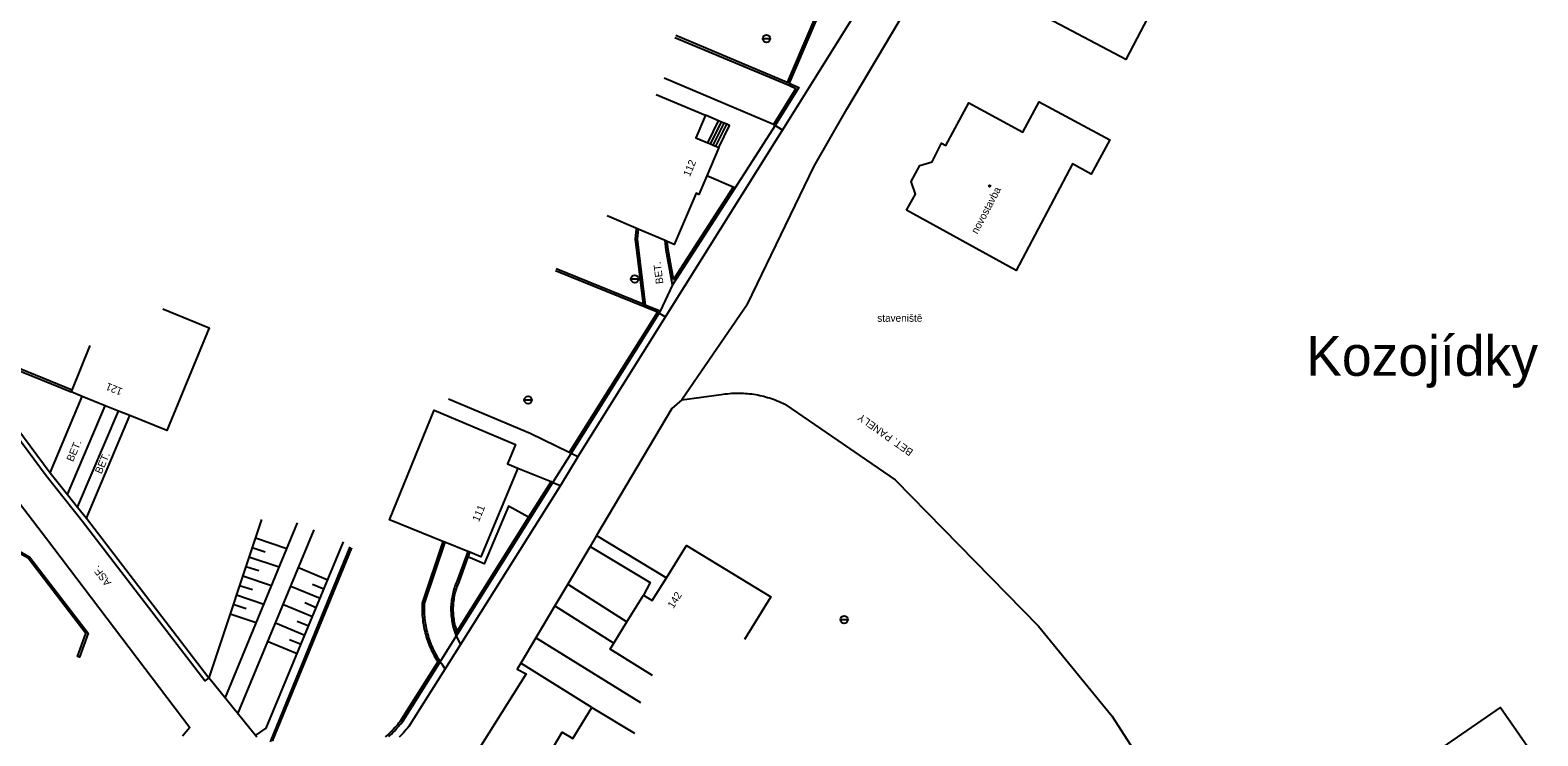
# Model space of a CAD drawing. Extents: x -544674 to -541478, y -1199076 to -1195527.
# Drawn here: x -543774 to -543623.1, y -1197058.3 to -1196987.7 of the extents above; entities that cross this region are included whole.
import ezdxf

# ---------------------------------------------------------------- set-up
doc = ezdxf.new("R2010")
doc.units = 0
for name, color, linetype in [('BUDOVY_MĚŘ', 7, 'Continuous'), ('BUDOVY_NEMĚŘ', 7, 'Continuous'), ('NÁZVY_SÍDEL_JEDNOTKY', 7, 'Continuous'), ('POMOC_POPIS', 7, 'Continuous'), ('ROZHRANÍ_PLOCH', 7, 'Continuous'), ('VÝŠKOPIS', 7, 'Continuous'), ('ZN_BUDOV', 7, 'Continuous'), ('ZN_DOPLŇKOVÉ', 7, 'Continuous'), ('Č_POPIS_ORIENT', 7, 'Continuous')]:
    doc.layers.add(name, color=color, linetype=linetype)

msp = doc.modelspace()

# ---------------------------------------------------------------- linework, layer by layer
at = {"layer": 'BUDOVY_MĚŘ'}
for points in [[(-543675.17, -1196984.9), (-543673.76, -1196981.94), (-543671.67, -1196978.25), (-543667.07, -1196980.67), (-543665.24, -1196977.07), (-543658.12, -1196980.83), (-543660.21, -1196984.79), (-543661.09, -1196984.33), (-543664.37, -1196990.58), (-543675.17, -1196984.9)], [(-543711.37, -1196994.08), (-543706.44, -1196996.17)], [(-543686.31, -1197005.69), (-543685.4, -1197004.07), (-543685.83, -1197002.8), (-543684.98, -1197001.22), (-543683.73, -1197000.85), (-543682.79, -1196998.98), (-543682.36, -1196999.2), (-543680.07, -1196994.92), (-543674.66, -1196997.85), (-543673.02, -1196994.82), (-543665.97, -1196998.64), (-543667.82, -1197002.06), (-543669.69, -1197001.05), (-543675.32, -1197011.72), (-543686.31, -1197005.69)], [(-543706.44, -1196996.17), (-543707.4, -1196998.42), (-543706.21, -1196998.93)], [(-543705.1, -1196999.4), (-543706.31, -1197002.24)], [(-543706.21, -1196998.93), (-543705.93, -1196999.05)], [(-543705.93, -1196999.05), (-543705.65, -1196999.17)], [(-543705.65, -1196999.17), (-543705.38, -1196999.28)], [(-543705.38, -1196999.28), (-543705.1, -1196999.4)], [(-543706.31, -1197002.24), (-543707.1, -1197004.11), (-543707.37, -1197003.99), (-543709.55, -1197009.12), (-543710.27, -1197008.81)], [(-543713.15, -1197007.58), (-543716.28, -1197006.24)], [(-543710.48, -1197008.72), (-543713.15, -1197007.58)], [(-543710.27, -1197008.81), (-543710.48, -1197008.72)], [(-543760.74, -1197015.54), (-543756.11, -1197017.44), (-543760.33, -1197027.73), (-543764.03, -1197026.24)], [(-543769.83, -1197023.68), (-543768.02, -1197019.24)], [(-543769.91, -1197023.87), (-543769.83, -1197023.68)], [(-543768.81, -1197024.32), (-543769.91, -1197023.87)], [(-543766.51, -1197025.25), (-543768.81, -1197024.32)], [(-543765.19, -1197025.79), (-543766.51, -1197025.25)], [(-543764.03, -1197026.24), (-543765.19, -1197025.79)], [(-543732.7, -1197038.86), (-543738.05, -1197036.69), (-543733.6, -1197025.71), (-543725.43, -1197029.13), (-543726.25, -1197031.08), (-543725.21, -1197031.52)], [(-543725.21, -1197031.52), (-543728.92, -1197040.37), (-543730.03, -1197039.93)], [(-543732.52, -1197038.93), (-543732.7, -1197038.86)], [(-543730.22, -1197039.86), (-543732.52, -1197038.93)], [(-543710.33, -1197042.48), (-543708.32, -1197039.25), (-543699.9, -1197044.4), (-543702.51, -1197048.67)], [(-543730.03, -1197039.93), (-543730.22, -1197039.86)], [(-543712.62, -1197044.22), (-543711.76, -1197044.76), (-543710.33, -1197042.48)], [(-543714.29, -1197046.89), (-543712.62, -1197044.22)], [(-543715.61, -1197049.01), (-543714.29, -1197046.89)], [(-543711.74, -1197052.25), (-543715.98, -1197049.61), (-543715.61, -1197049.01)], [(-543720.39, -1197069.07), (-543724.62, -1197066.41), (-543721.51, -1197061.46), (-543722.52, -1197060.86), (-543720.76, -1197057.95), (-543719.72, -1197058.58), (-543717.82, -1197055.45)], [(-543717.82, -1197055.45), (-543713.54, -1197058.04)]]:
    msp.add_lwpolyline(points, dxfattribs=at)
at = {"layer": 'BUDOVY_NEMĚŘ'}
msp.add_lwpolyline([(-543643.2, -1197066.76), (-543626.85, -1197055.47), (-543623.36, -1197060.52), (-543634.05, -1197067.92), (-543631.88, -1197071.18), (-543629.12, -1197069.29), (-543626.81, -1197072.64), (-543634.02, -1197077.58)], dxfattribs=at)
at = {"layer": 'ROZHRANÍ_PLOCH'}
for points in [[(-543702.21, -1197015.1), (-543695.55, -1197001.26), (-543692.29, -1196995.55), (-543685.48, -1196984.08), (-543681.27, -1196978.03)], [(-543698.72, -1196997.66), (-543690.05, -1196983.74)], [(-543756.14, -1197052.5), (-543756.54, -1197052.8), (-543768.8, -1197036.81), (-543772.42, -1197032.27), (-543779.2, -1197023.15), (-543791.56, -1197007.3), (-543803.53, -1196991.7)], [(-543699.63, -1196997.09), (-543710.56, -1196992.45)], [(-543705.12, -1196996.73), (-543706.44, -1196996.17)], [(-543706.21, -1196998.93), (-543705.12, -1196996.73)], [(-543705.93, -1196999.05), (-543704.84, -1196996.85)], [(-543705.65, -1196999.17), (-543704.56, -1196996.97)], [(-543705.38, -1196999.28), (-543704.29, -1196997.08)], [(-543704.84, -1196996.85), (-543705.12, -1196996.73)], [(-543705.1, -1196999.4), (-543704.01, -1196997.2), (-543704.29, -1196997.08)], [(-543704.56, -1196996.97), (-543704.84, -1196996.85)], [(-543704.29, -1196997.08), (-543704.56, -1196996.97)], [(-543710.43, -1197016.37), (-543699.35, -1196998.67), (-543698.72, -1196997.66)], [(-543698.72, -1196997.66), (-543699.46, -1196997.2)], [(-543703.66, -1197003.36), (-543706.31, -1197002.24)], [(-543703.47, -1197003.44), (-543703.66, -1197003.36)], [(-543709.72, -1197013.15), (-543710.96, -1197015.79)], [(-543702.21, -1197015.1), (-543708.79, -1197024.67)], [(-543789.82, -1197015.89), (-543786.14, -1197020.59), (-543772.39, -1197038.54), (-543758.03, -1197057.48), (-543758.78, -1197058.34)], [(-543719.19, -1197030.38), (-543710.43, -1197016.37)], [(-543710.96, -1197015.79), (-543711.05, -1197015.98)], [(-543711.05, -1197015.98), (-543710.43, -1197016.37)], [(-543778.81, -1197022.84), (-543772.01, -1197031.98)], [(-543772.01, -1197031.98), (-543768.81, -1197024.32)], [(-543708.79, -1197024.67), (-543704.85, -1197024.13), (-543704.65, -1197024.1), (-543704.45, -1197024.07), (-543704.24, -1197024.05), (-543704.04, -1197024.03), (-543703.84, -1197024.01), (-543703.63, -1197024), (-543703.43, -1197024), (-543703.23, -1197023.99), (-543703.02, -1197023.99), (-543702.82, -1197024), (-543702.62, -1197024.01), (-543702.41, -1197024.02), (-543702.21, -1197024.03), (-543702.01, -1197024.06), (-543701.8, -1197024.08), (-543701.6, -1197024.11), (-543701.4, -1197024.14), (-543701.2, -1197024.18), (-543701, -1197024.22), (-543700.8, -1197024.26), (-543700.6, -1197024.31), (-543700.41, -1197024.36), (-543700.21, -1197024.42), (-543700.01, -1197024.48), (-543699.82, -1197024.54), (-543699.63, -1197024.61), (-543699.44, -1197024.68), (-543699.25, -1197024.76), (-543699.06, -1197024.83), (-543698.87, -1197024.92), (-543698.69, -1197025), (-543698.5, -1197025.09), (-543698.39, -1197025.15), (-543687.46, -1197032.66), (-543673.1, -1197047.31), (-543665.76, -1197056.31), (-543660.89, -1197063.88)], [(-543770.28, -1197034.15), (-543766.51, -1197025.25)], [(-543769.27, -1197035.41), (-543765.19, -1197025.79)], [(-543720.06, -1197029.95), (-543723.98, -1197028.02), (-543732.15, -1197024.6)], [(-543708.79, -1197024.67), (-543709.78, -1197025.54), (-543717.33, -1197038.26)], [(-543768.39, -1197036.52), (-543764.03, -1197026.24)], [(-543719.88, -1197030.04), (-543720.06, -1197029.95)], [(-543719.19, -1197030.38), (-543719.88, -1197030.04)], [(-543725.21, -1197031.52), (-543721.89, -1197032.85)], [(-543719.19, -1197030.38), (-543720.95, -1197033.23)], [(-543772.01, -1197031.98), (-543770.28, -1197034.15)], [(-543720.95, -1197033.23), (-543730.95, -1197049.15), (-543732.48, -1197051.58)], [(-543721.89, -1197032.85), (-543721.7, -1197032.93)], [(-543721.7, -1197032.93), (-543720.95, -1197033.23)], [(-543770.28, -1197034.15), (-543769.27, -1197035.41)], [(-543769.27, -1197035.41), (-543768.39, -1197036.52)], [(-543724.13, -1197036.41), (-543726.16, -1197035.31), (-543728.58, -1197041.07), (-543730.2, -1197040.39)], [(-543768.39, -1197036.52), (-543756.14, -1197052.5)], [(-543717.97, -1197039.34), (-543720.22, -1197043.13)], [(-543717.33, -1197038.26), (-543717.97, -1197039.34)], [(-543717.97, -1197039.34), (-543711.95, -1197042.96), (-543712.62, -1197044.22)], [(-543717.33, -1197038.26), (-543710.33, -1197042.48)], [(-543720.22, -1197043.13), (-543721.5, -1197045.28)], [(-543720.22, -1197043.13), (-543714.29, -1197046.89)], [(-543721.5, -1197045.28), (-543723.4, -1197048.48)], [(-543721.5, -1197045.28), (-543715.61, -1197049.01)], [(-543723.4, -1197048.48), (-543724.92, -1197051.03)], [(-543712.89, -1197055.01), (-543723.4, -1197048.48)], [(-543724.92, -1197051.03), (-543725.28, -1197051.64), (-543724.39, -1197052.08), (-543729.99, -1197060.99)], [(-543717.82, -1197055.45), (-543724.92, -1197051.03)], [(-543751.34, -1197058.43), (-543751.47, -1197058.27), (-543756.14, -1197052.5)], [(-543732.48, -1197051.58), (-543736.01, -1197057.2), (-543736.13, -1197057.36), (-543736.26, -1197057.52), (-543736.39, -1197057.68), (-543736.53, -1197057.84), (-543736.66, -1197057.99), (-543736.8, -1197058.14), (-543736.94, -1197058.29), (-543737.09, -1197058.44)]]:
    msp.add_lwpolyline(points, dxfattribs=at)
at = {"layer": 'VÝŠKOPIS'}
for points in [[(-543748.32, -1197039.58), (-543751.48, -1197038.53)], [(-543749.09, -1197041.43), (-543752.12, -1197040.42)], [(-543750.51, -1197039.9), (-543751.8, -1197039.47)], [(-543749.86, -1197043.28), (-543752.75, -1197042.32)], [(-543751.14, -1197041.8), (-543752.43, -1197041.37)], [(-543747.15, -1197041.46), (-543744.23, -1197042.67)], [(-543751.78, -1197043.7), (-543753.06, -1197043.27)], [(-543747.92, -1197043.31), (-543745, -1197044.51)], [(-543745.77, -1197043.11), (-543744.61, -1197043.59)], [(-543752.41, -1197045.6), (-543753.7, -1197045.17)], [(-543750.62, -1197045.14), (-543753.38, -1197044.22)], [(-543748.68, -1197045.15), (-543745.76, -1197046.36)], [(-543746.53, -1197044.96), (-543745.38, -1197045.44)], [(-543751.39, -1197046.99), (-543754.01, -1197046.12)], [(-543747.29, -1197046.81), (-543746.14, -1197047.29)], [(-543749.45, -1197047), (-543746.53, -1197048.21)], [(-543750.21, -1197048.85), (-543747.29, -1197050.06)], [(-543748.06, -1197048.66), (-543746.91, -1197049.14)]]:
    msp.add_lwpolyline(points, dxfattribs=at)
at = {"layer": 'ZN_BUDOV'}
msp.add_circle((-543677.99, -1197003.26), 0.0875, dxfattribs=at)
at = {"layer": 'ZN_DOPLŇKOVÉ'}
for p, q in [((-543700.695, -1196988.5), (-543699.945, -1196988.5)), ((-543713.885, -1197012.56), (-543713.135, -1197012.56)), ((-543724.565, -1197024.68), (-543723.815, -1197024.68)), ((-543692.925, -1197046.67), (-543692.175, -1197046.67))]:
    msp.add_line(p, q, dxfattribs=at)
for points in [[(-543693.61, -1196982), (-543698.24, -1196992.88)], [(-543693.42, -1196982.08), (-543698.06, -1196992.96)], [(-543709.48, -1196988.38), (-543698.14, -1196993.14), (-543697.38, -1196993.49), (-543699.63, -1196997.09)], [(-543698.24, -1196992.88), (-543709.4, -1196988.2)], [(-543698.06, -1196992.96), (-543697.09, -1196993.4), (-543699.46, -1196997.2)], [(-543698.06, -1196992.96), (-543698.24, -1196992.88)], [(-543699.63, -1196997.09), (-543699.46, -1196997.2)], [(-543699.46, -1196997.2), (-543703.47, -1197003.44)], [(-543703.66, -1197003.36), (-543709.62, -1197012.62), (-543710.18, -1197009.65), (-543710.27, -1197008.81)], [(-543703.47, -1197003.44), (-543709.72, -1197013.15)], [(-543713.35, -1197007.56), (-543713.46, -1197008.59), (-543712.67, -1197015.09)], [(-543713.15, -1197007.58), (-543713.26, -1197008.59), (-543712.46, -1197015.18)], [(-543709.72, -1197013.15), (-543710.38, -1197009.68), (-543710.48, -1197008.72)], [(-543710.27, -1197008.81), (-543710.28, -1197008.7)], [(-543711.24, -1197015.9), (-543721.45, -1197011.75)], [(-543712.67, -1197015.09), (-543721.37, -1197011.56)], [(-543712.46, -1197015.18), (-543712.67, -1197015.09)], [(-543710.96, -1197015.79), (-543712.46, -1197015.18)], [(-543711.24, -1197015.9), (-543720.06, -1197029.95)], [(-543719.88, -1197030.04), (-543711.05, -1197015.98)], [(-543711.05, -1197015.98), (-543711.24, -1197015.9)], [(-543769.83, -1197023.68), (-543777.92, -1197020.4), (-543778.95, -1197022.66)], [(-543778.81, -1197022.84), (-543777.82, -1197020.66), (-543769.91, -1197023.87)], [(-543721.7, -1197032.93), (-543719.88, -1197030.04)], [(-543731.24, -1197048.11), (-543721.7, -1197032.93)], [(-543721.89, -1197032.85), (-543724.13, -1197036.41)], [(-543724.13, -1197036.41), (-543731.32, -1197047.87)], [(-543750.85, -1197036.63), (-543756.14, -1197052.5)], [(-543754.51, -1197054.52), (-543747.25, -1197036.99)], [(-543753.22, -1197056.11), (-543745.59, -1197037.68)], [(-543777.55, -1197038.46), (-543774.09, -1197040.38), (-543768.23, -1197048.03), (-543769.09, -1197050.42), (-543769.28, -1197050.35), (-543768.45, -1197048.06), (-543774.22, -1197040.53), (-543777.65, -1197038.63), (-543777.55, -1197038.46)], [(-543751.47, -1197058.27), (-543750.39, -1197057.55), (-543742.67, -1197038.89)], [(-543742.02, -1197039.39), (-543750, -1197058.9)], [(-543732.7, -1197038.86), (-543734.78, -1197045.02), (-543734.79, -1197045.25), (-543734.79, -1197045.45), (-543734.79, -1197045.65), (-543734.79, -1197045.85), (-543734.78, -1197046.05), (-543734.77, -1197046.24), (-543734.75, -1197046.44), (-543734.73, -1197046.64), (-543734.71, -1197046.84), (-543734.68, -1197047.03), (-543734.65, -1197047.23), (-543734.61, -1197047.43), (-543734.57, -1197047.62), (-543734.53, -1197047.81), (-543734.48, -1197048.01), (-543734.43, -1197048.2), (-543734.37, -1197048.39), (-543734.31, -1197048.58), (-543734.25, -1197048.77), (-543734.19, -1197048.95), (-543734.11, -1197049.14), (-543734.04, -1197049.32), (-543733.96, -1197049.5), (-543733.88, -1197049.69), (-543733.8, -1197049.87), (-543733.71, -1197050.04), (-543733.61, -1197050.22), (-543733.52, -1197050.39), (-543733.42, -1197050.57), (-543733.32, -1197050.73), (-543733.21, -1197050.9)], [(-543732.52, -1197038.93), (-543734.58, -1197045.06), (-543734.59, -1197045.18), (-543734.59, -1197045.38), (-543734.59, -1197045.58), (-543734.59, -1197045.77), (-543734.58, -1197045.97), (-543734.57, -1197046.16), (-543734.56, -1197046.36), (-543734.54, -1197046.56), (-543734.52, -1197046.75), (-543734.49, -1197046.95), (-543734.46, -1197047.14), (-543734.43, -1197047.33), (-543734.39, -1197047.53), (-543734.35, -1197047.72), (-543734.3, -1197047.91), (-543734.25, -1197048.1), (-543734.19, -1197048.29), (-543734.14, -1197048.48), (-543734.08, -1197048.66), (-543734.01, -1197048.85), (-543733.94, -1197049.03), (-543733.87, -1197049.21), (-543733.79, -1197049.4), (-543733.71, -1197049.58), (-543733.63, -1197049.75), (-543733.54, -1197049.93), (-543733.45, -1197050.1), (-543733.36, -1197050.27), (-543733.26, -1197050.45), (-543733.16, -1197050.61), (-543733.05, -1197050.78), (-543732.98, -1197050.88)], [(-543749.76, -1197058.83), (-543741.83, -1197039.47)], [(-543730.22, -1197039.86), (-543731.31, -1197042.84), (-543731.38, -1197042.99), (-543731.44, -1197043.15), (-543731.5, -1197043.31), (-543731.55, -1197043.46), (-543731.6, -1197043.62), (-543731.65, -1197043.78), (-543731.69, -1197043.95), (-543731.73, -1197044.11), (-543731.76, -1197044.27), (-543731.79, -1197044.44), (-543731.82, -1197044.6), (-543731.84, -1197044.77), (-543731.86, -1197044.93), (-543731.88, -1197045.1), (-543731.89, -1197045.26), (-543731.9, -1197045.43), (-543731.9, -1197045.6), (-543731.9, -1197045.77), (-543731.89, -1197045.93), (-543731.88, -1197046.1), (-543731.87, -1197046.27), (-543731.85, -1197046.43), (-543731.83, -1197046.6), (-543731.81, -1197046.76), (-543731.78, -1197046.93), (-543731.75, -1197047.09), (-543731.71, -1197047.25), (-543731.67, -1197047.42), (-543731.41, -1197048.21), (-543731.37, -1197048.32)], [(-543730.2, -1197040.39), (-543731.13, -1197042.92), (-543731.19, -1197043.07), (-543731.25, -1197043.22), (-543731.31, -1197043.38), (-543731.36, -1197043.53), (-543731.41, -1197043.69), (-543731.45, -1197043.85), (-543731.5, -1197044), (-543731.54, -1197044.17), (-543731.57, -1197044.33), (-543731.6, -1197044.49), (-543731.63, -1197044.65), (-543731.65, -1197044.81), (-543731.67, -1197044.98), (-543731.68, -1197045.14), (-543731.69, -1197045.31), (-543731.7, -1197045.47), (-543731.7, -1197045.64), (-543731.7, -1197045.8), (-543731.69, -1197045.97), (-543731.68, -1197046.13), (-543731.67, -1197046.29), (-543731.65, -1197046.46), (-543731.63, -1197046.62), (-543731.6, -1197046.78), (-543731.57, -1197046.95), (-543731.54, -1197047.11), (-543731.5, -1197047.27), (-543731.46, -1197047.43), (-543731.32, -1197047.87)], [(-543730.03, -1197039.93), (-543730.2, -1197040.39)], [(-543732.98, -1197050.88), (-543731.37, -1197048.32)], [(-543731.37, -1197048.32), (-543731.24, -1197048.11)], [(-543731.37, -1197048.32), (-543730.95, -1197049.15)], [(-543731.32, -1197047.87), (-543731.24, -1197048.11)], [(-543733.21, -1197050.9), (-543736.27, -1197055.73), (-543737.02, -1197056.89), (-543737.14, -1197057.04), (-543737.26, -1197057.19), (-543737.51, -1197057.48), (-543737.64, -1197057.62), (-543737.78, -1197057.76), (-543737.91, -1197057.9), (-543738.05, -1197058.03), (-543738.19, -1197058.16), (-543738.34, -1197058.29), (-543738.48, -1197058.41)], [(-543738.13, -1197058.38), (-543737.99, -1197058.25), (-543737.85, -1197058.12), (-543737.71, -1197057.98), (-543737.57, -1197057.84), (-543737.44, -1197057.7), (-543737.31, -1197057.55), (-543737.18, -1197057.41), (-543736.93, -1197057.11), (-543736.7, -1197056.79), (-543733.1, -1197051.07)], [(-543733.21, -1197050.9), (-543733.1, -1197051.07)], [(-543733.1, -1197051.07), (-543732.98, -1197050.88)], [(-543732.98, -1197050.88), (-543732.94, -1197050.94), (-543732.83, -1197051.11), (-543732.72, -1197051.26), (-543732.6, -1197051.42), (-543732.48, -1197051.58)]]:
    msp.add_lwpolyline(points, dxfattribs=at)
for centre in [(-543700.32, -1196988.5), (-543713.51, -1197012.56), (-543724.19, -1197024.68), (-543692.55, -1197046.67)]:
    msp.add_circle(centre, 0.375, dxfattribs=at)

# ---------------------------------------------------------------- texts
at = {"layer": 'NÁZVY_SÍDEL_JEDNOTKY'}
msp.add_text('Kozojídky', height=4, dxfattribs=at).set_placement((-543646.3, -1197022.26))
at = {"layer": 'POMOC_POPIS'}
for s, rotation, p in [('novostavba', 62.14002, (-543679.22, -1197008.12)), ('BET.', 96.93999, (-543710.64, -1197013.02)), ('BET. PANELY', 144.78002, (-543685.57, -1197029.73)), ('BET.', 67.02002, (-543769.73, -1197030.92)), ('BET.', 67.02002, (-543766.88, -1197032.14)), ('ASF.', 127.46999, (-543765.86, -1197042.96))]:
    msp.add_text(s, height=0.75, rotation=rotation, dxfattribs=at).set_placement(p)
msp.add_text('staveniště', height=0.75, dxfattribs=at).set_placement((-543689.24, -1197016.85))
at = {"layer": 'Č_POPIS_ORIENT'}
for s, rotation, p in [('112', 66.99, (-543708, -1197002.38)), ('121', 157.75001, (-543764.7, -1197023.56)), ('111', 67.25997, (-543729.11, -1197036.93)), ('142', 58.05999, (-543709.64, -1197045.61))]:
    msp.add_text(s, height=0.75, rotation=rotation, dxfattribs=at).set_placement(p)

doc.saveas('drawing.dxf')
